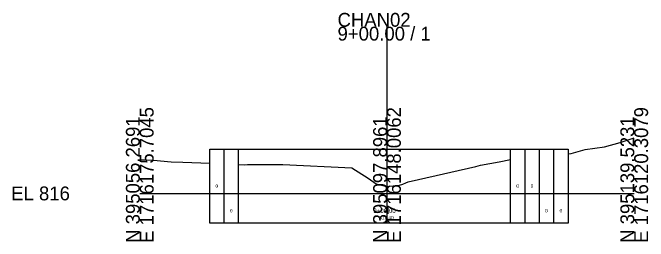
# Model space of a CAD drawing. Extents: x -26 to 103, y -10 to 16052.
# Drawn here: x -25.7 to 102.8, y 1490.3 to 1536.6 of the extents above; entities that cross this region are included whole.
import ezdxf

# ---------------------------------------------------------------- set-up
doc = ezdxf.new("R2010")
doc.units = 0
for name, color, linetype in [('GK_Cells', 7, 'Continuous'), ('SH_Text', 7, 'Continuous'), ('XS_P_Annotation', 7, 'Continuous'), ('XS_P_Boundary', 7, 'Continuous'), ('XS_X_Ground_Line', 7, 'Continuous')]:
    doc.layers.add(name, color=color, linetype=linetype)

msp = doc.modelspace()

# ---------------------------------------------------------------- linework, layer by layer
at = {"layer": 'GK_Cells'}
for p, q in [((50, 1500), (50, 1533.75)), ((0, 1500), (50, 1500)), ((50, 1500), (100, 1500))]:
    msp.add_line(p, q, dxfattribs=at)
at = {"layer": 'XS_P_Boundary'}
for p, q in [((17.08, 1494.01), (17.08, 1508.99)), ((20, 1494.01), (20, 1508.99)), ((50, 1494.01), (50, 1508.99)), ((75, 1494.01), (75, 1508.99)), ((77.92, 1494.01), (77.92, 1508.99)), ((80.83, 1494.01), (80.83, 1508.99)), ((83.75, 1494.01), (83.75, 1508.99)), ((15.63, 1501.5), (15.63, 1501.5)), ((76.46, 1501.5), (76.46, 1501.5)), ((79.38, 1501.5), (79.38, 1501.5)), ((18.54, 1496.51), (18.54, 1496.51)), ((82.29, 1496.51), (82.29, 1496.51)), ((85.21, 1496.51), (85.21, 1496.51))]:
    msp.add_line(p, q, dxfattribs=at)
msp.add_lwpolyline([(14.17, 1494.01), (14.17, 1508.99), (86.67, 1508.99), (86.67, 1494.01)], close=True, dxfattribs=at)
at = {"layer": 'XS_X_Ground_Line'}
for points in [[(86.67, 1508.01), (87.21, 1508.11), (90.07, 1508.87), (93.96, 1509.46), (97.17, 1510.3), (100, 1511.25)], [(0, 1506.88), (2.75, 1506.76), (6.32, 1506.42), (8.69, 1506.33), (14.17, 1506.1)], [(20, 1505.87), (21.12, 1505.82), (21.79, 1505.85), (23.73, 1505.85), (26.47, 1505.86), (26.95, 1505.85), (28.92, 1505.84), (42.9, 1505.18), (46.18, 1503.11), (47.8, 1501.95), (49.46, 1501.52), (49.91, 1501.39), (52.52, 1501.64), (53.18, 1501.88), (53.78, 1502.13), (54.31, 1502.36), (56.4, 1502.83), (67.99, 1505.46), (68.92, 1505.74), (72.7, 1506.38), (75, 1506.84)]]:
    msp.add_lwpolyline(points, dxfattribs=at)

# ---------------------------------------------------------------- texts
at = {"layer": 'GK_Cells'}
for s, p in [('CHAN02', (40, 1533.75)), ('9+00.00 / 1', (40, 1530.95)), ('EL 816', (-26, 1498.6))]:
    msp.add_text(s, height=2.8, dxfattribs=at).set_placement(p)
for s, p in [('E 1716175.7045', (2.8, 1490)), ('E 1716148.0062', (52.8, 1490)), ('E 1716120.3079', (102.8, 1490)), ('N 395056.2691', (0, 1490)), ('N 395097.8961', (50, 1490)), ('N 395139.5231', (100, 1490))]:
    msp.add_text(s, height=2.8, rotation=90, dxfattribs=at).set_placement(p)
at = {"layer": 'SH_Text'}
for p in [(15.31, 1501.15), (76.14, 1501.15), (79.06, 1501.15), (18.23, 1496.16), (81.98, 1496.16), (84.9, 1496.16)]:
    msp.add_text('0', height=0.7, dxfattribs=at).set_placement(p)
at = {"layer": 'XS_P_Annotation'}
for s, height, p in [('9+00.00', 0.9, (47.23, 1496.05)), ('817.40', 0.7, (48.4, 1494.75))]:
    msp.add_text(s, height=height, dxfattribs=at).set_placement(p)

doc.saveas('drawing.dxf')
